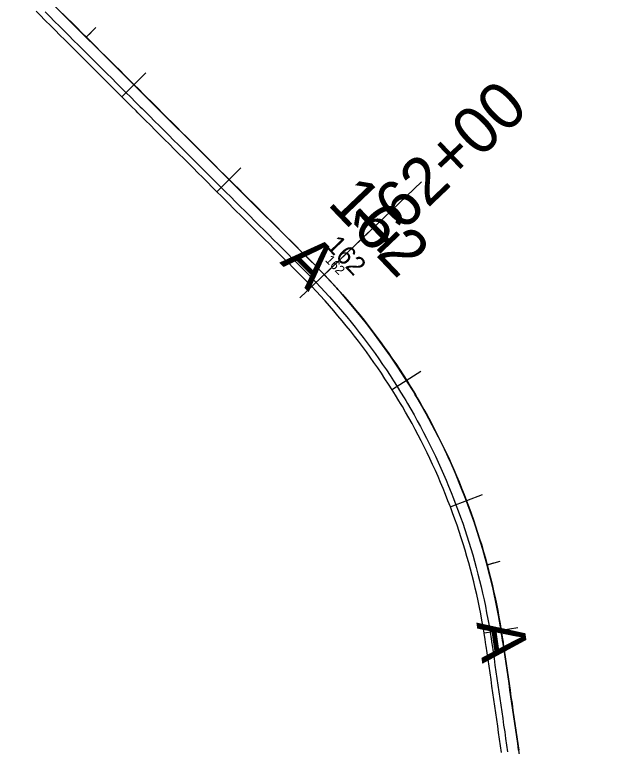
# Model space of a CAD drawing. Extents: x 1823824 to 1861612, y 706975 to 726130.
# Drawn here: x 1826051.2 to 1826141.7, y 715288.9 to 715397.8 of the extents above; entities that cross this region are included whole.
import ezdxf

# ---------------------------------------------------------------- set-up
doc = ezdxf.new("R2010")
doc.units = 0
for name, color, linetype in [('DR_X_Flood_Boundary', 7, 'Continuous'), ('GE_X_CL_10', 7, 'Continuous'), ('GE_X_CL_100', 7, 'Continuous'), ('GE_X_CL_20', 7, 'Continuous'), ('GE_X_CL_200', 7, 'Continuous'), ('GE_X_CL_50', 7, 'Continuous'), ('SC_Scratch3', 7, 'Continuous'), ('SC_Scratch5', 7, 'Continuous'), ('SC_Scratch6', 7, 'Continuous')]:
    doc.layers.add(name, color=color, linetype=linetype)

msp = doc.modelspace()

# ---------------------------------------------------------------- linework, layer by layer
at = {"layer": 'DR_X_Flood_Boundary'}
for p, q in [((1826051.17, 715405.06), (1826095.44, 715360.91)), ((1826123.8, 715304.42), (1826141.7, 715180.65))]:
    msp.add_line(p, q, dxfattribs=at)
msp.add_arc((1826024.83, 715290.1), 100, 8.2313, 45.0774, dxfattribs=at)
at = {"layer": 'GE_X_CL_10'}
for p, q in [((1826061.82, 715394.44), (1826062.53, 715395.15)), ((1826097.2, 715359.11), (1826097.93, 715359.8)), ((1826121.43, 715315.96), (1826122.39, 715316.22))]:
    msp.add_line(p, q, dxfattribs=at)
at = {"layer": 'GE_X_CL_100'}
msp.add_line((1826097.2, 715359.11), (1826104.44, 715366.01), dxfattribs=at)
at = {"layer": 'GE_X_CL_20'}
for p, q in [((1826061.82, 715394.44), (1826063.23, 715395.86)), ((1826097.2, 715359.11), (1826098.65, 715360.49)), ((1826121.43, 715315.96), (1826123.36, 715316.48))]:
    msp.add_line(p, q, dxfattribs=at)
at = {"layer": 'GE_X_CL_200'}
msp.add_line((1826097.2, 715359.11), (1826111.68, 715372.91), dxfattribs=at)
at = {"layer": 'GE_X_CL_50'}
msp.add_line((1826097.2, 715359.11), (1826100.82, 715362.56), dxfattribs=at)
at = {"layer": 'SC_Scratch3'}
for points in [[(1826110.74, 715336.1), (1826110.27, 715336.96), (1826109.8, 715337.81), (1826109.32, 715338.66), (1826108.83, 715339.5), (1826108.56, 715339.95), (1826108.33, 715340.34), (1826107.82, 715341.17), (1826107.31, 715342), (1826106.79, 715342.82), (1826106.25, 715343.63), (1826105.71, 715344.45), (1826105.17, 715345.25), (1826104.61, 715346.05), (1826104.05, 715346.85), (1826103.48, 715347.64), (1826102.9, 715348.42), (1826102.31, 715349.2), (1826101.72, 715349.97), (1826101.11, 715350.74), (1826100.5, 715351.5), (1826099.89, 715352.25), (1826099.26, 715353), (1826098.63, 715353.74), (1826097.99, 715354.47), (1826097.34, 715355.2), (1826097.19, 715355.37), (1826096.69, 715355.92), (1826096.02, 715356.64), (1826095.35, 715357.35), (1826094.68, 715358.05), (1826094, 715358.74), (1826093.64, 715359.1), (1826093.3, 715359.44), (1826092.59, 715360.15), (1826091.88, 715360.85), (1826091.17, 715361.56), (1826090.47, 715362.27), (1826089.76, 715362.97), (1826089.05, 715363.68), (1826088.34, 715364.39), (1826087.63, 715365.09), (1826086.93, 715365.8), (1826086.22, 715366.5), (1826085.51, 715367.21), (1826084.8, 715367.92), (1826084.09, 715368.62), (1826083.44, 715369.27), (1826083.39, 715369.33), (1826082.68, 715370.03), (1826081.97, 715370.74), (1826081.26, 715371.45), (1826080.55, 715372.15), (1826079.84, 715372.86), (1826079.14, 715373.57), (1826078.43, 715374.27), (1826077.72, 715374.98), (1826077.01, 715375.68), (1826076.31, 715376.39), (1826075.6, 715377.1), (1826074.89, 715377.8), (1826074.18, 715378.51), (1826073.47, 715379.22), (1826072.77, 715379.92), (1826072.06, 715380.63), (1826071.35, 715381.34), (1826070.64, 715382.04), (1826069.94, 715382.75), (1826069.51, 715383.18), (1826069.23, 715383.46), (1826068.52, 715384.16), (1826067.81, 715384.87), (1826067.11, 715385.58), (1826066.4, 715386.28), (1826065.69, 715386.99), (1826064.98, 715387.7), (1826064.28, 715388.4), (1826063.57, 715389.11), (1826062.86, 715389.82), (1826062.15, 715390.52), (1826061.45, 715391.23), (1826060.74, 715391.94), (1826060.03, 715392.64), (1826059.32, 715393.35), (1826058.62, 715394.06), (1826057.91, 715394.76), (1826057.2, 715395.47), (1826056.49, 715396.17), (1826055.78, 715396.88), (1826055.57, 715397.09), (1826055.08, 715397.59), (1826054.37, 715398.29)], [(1826055.69, 715398.21), (1826056.19, 715397.71), (1826056.4, 715397.5), (1826057.11, 715396.79), (1826057.82, 715396.09), (1826058.53, 715395.38), (1826059.23, 715394.68), (1826059.94, 715393.97), (1826060.65, 715393.26), (1826061.36, 715392.56), (1826062.07, 715391.85), (1826062.77, 715391.15), (1826063.48, 715390.44), (1826064.19, 715389.73), (1826064.9, 715389.03)], [(1826113, 715337.31), (1826112.52, 715338.19), (1826112.03, 715339.06), (1826111.54, 715339.93), (1826111.04, 715340.8), (1826110.76, 715341.26), (1826110.53, 715341.66), (1826110.01, 715342.51), (1826109.48, 715343.36), (1826108.94, 715344.2), (1826108.4, 715345.04), (1826107.84, 715345.88), (1826107.28, 715346.7), (1826106.71, 715347.52), (1826106.13, 715348.34), (1826105.55, 715349.15), (1826104.95, 715349.96), (1826104.35, 715350.75), (1826103.74, 715351.55), (1826103.12, 715352.33), (1826102.49, 715353.11), (1826101.86, 715353.88), (1826101.22, 715354.65), (1826100.57, 715355.41), (1826099.91, 715356.17), (1826099.25, 715356.91), (1826099.09, 715357.09), (1826098.58, 715357.66), (1826097.9, 715358.39), (1826097.21, 715359.12), (1826096.52, 715359.84), (1826095.82, 715360.55), (1826095.45, 715360.92), (1826095.11, 715361.26), (1826094.4, 715361.96), (1826093.69, 715362.67), (1826092.98, 715363.38), (1826092.28, 715364.08), (1826091.57, 715364.79), (1826090.86, 715365.49), (1826090.15, 715366.2), (1826089.44, 715366.91), (1826088.74, 715367.61), (1826088.03, 715368.32), (1826087.32, 715369.02), (1826086.61, 715369.73), (1826085.9, 715370.44), (1826085.25, 715371.09), (1826085.2, 715371.14), (1826084.49, 715371.85), (1826083.78, 715372.56), (1826083.07, 715373.26), (1826082.36, 715373.97), (1826081.66, 715374.67), (1826080.95, 715375.38), (1826080.24, 715376.09), (1826079.53, 715376.79), (1826078.82, 715377.5), (1826078.11, 715378.2), (1826077.41, 715378.91), (1826076.7, 715379.62), (1826075.99, 715380.32), (1826075.28, 715381.03), (1826074.57, 715381.74), (1826073.87, 715382.44), (1826073.16, 715383.15), (1826072.45, 715383.85), (1826071.74, 715384.56), (1826071.31, 715384.99), (1826071.03, 715385.27), (1826070.33, 715385.97), (1826069.62, 715386.68), (1826068.91, 715387.38), (1826068.2, 715388.09), (1826067.49, 715388.8), (1826066.79, 715389.5), (1826066.08, 715390.21), (1826065.37, 715390.92), (1826064.66, 715391.62), (1826063.95, 715392.33), (1826063.25, 715393.03), (1826062.54, 715393.74), (1826061.83, 715394.45), (1826061.12, 715395.15), (1826060.41, 715395.86), (1826059.71, 715396.56), (1826059, 715397.27), (1826058.29, 715397.98)], [(1826058.3, 715397.98), (1826059, 715397.28), (1826059.71, 715396.57), (1826060.42, 715395.86), (1826061.13, 715395.16), (1826061.84, 715394.45), (1826062.54, 715393.75), (1826063.25, 715393.04), (1826063.96, 715392.33), (1826064.67, 715391.63), (1826065.38, 715390.92), (1826066.08, 715390.22)], [(1826066.08, 715390.22), (1826066.79, 715389.51), (1826067.5, 715388.8), (1826068.21, 715388.1), (1826068.92, 715387.39), (1826069.62, 715386.69), (1826070.33, 715385.98), (1826071.04, 715385.27), (1826071.32, 715385), (1826071.75, 715384.57), (1826072.46, 715383.86), (1826073.16, 715383.15), (1826073.87, 715382.45), (1826074.58, 715381.74), (1826075.29, 715381.04), (1826076, 715380.33), (1826076.71, 715379.62), (1826077.41, 715378.92), (1826078.12, 715378.21), (1826078.83, 715377.51), (1826079.54, 715376.8), (1826080.25, 715376.09), (1826080.95, 715375.39), (1826081.66, 715374.68), (1826082.37, 715373.97), (1826083.08, 715373.27), (1826083.79, 715372.56), (1826084.49, 715371.86), (1826085.2, 715371.15), (1826085.26, 715371.09), (1826085.91, 715370.44), (1826086.62, 715369.74), (1826087.33, 715369.03), (1826088.03, 715368.33), (1826088.74, 715367.62), (1826089.45, 715366.91), (1826090.16, 715366.21), (1826090.87, 715365.5), (1826091.57, 715364.79), (1826092.28, 715364.09), (1826092.99, 715363.38), (1826093.7, 715362.68), (1826094.41, 715361.97), (1826095.11, 715361.26), (1826095.46, 715360.92), (1826095.82, 715360.56), (1826096.52, 715359.84), (1826097.22, 715359.12), (1826097.9, 715358.4), (1826098.58, 715357.66), (1826099.1, 715357.09), (1826099.25, 715356.92), (1826099.92, 715356.17), (1826100.58, 715355.42), (1826101.23, 715354.66), (1826101.87, 715353.89), (1826102.5, 715353.12), (1826103.13, 715352.34), (1826103.75, 715351.55), (1826104.36, 715350.76), (1826104.96, 715349.96), (1826105.55, 715349.16), (1826106.14, 715348.35), (1826106.72, 715347.53), (1826107.29, 715346.71), (1826107.85, 715345.88), (1826108.4, 715345.05), (1826108.95, 715344.21), (1826109.49, 715343.37), (1826110.01, 715342.52), (1826110.53, 715341.66), (1826110.77, 715341.27), (1826111.05, 715340.8), (1826111.55, 715339.94), (1826112.04, 715339.07), (1826112.53, 715338.19), (1826113, 715337.31), (1826113.47, 715336.43), (1826113.93, 715335.54), (1826114.38, 715334.65), (1826114.82, 715333.75), (1826115.25, 715332.85), (1826115.68, 715331.94), (1826116.09, 715331.03), (1826116.49, 715330.12), (1826116.89, 715329.2), (1826117.28, 715328.28), (1826117.65, 715327.35), (1826118.02, 715326.42), (1826118.38, 715325.49), (1826118.73, 715324.55), (1826119.07, 715323.61), (1826119.4, 715322.66), (1826119.72, 715321.72), (1826120.03, 715320.77), (1826120.33, 715319.81), (1826120.63, 715318.86), (1826120.91, 715317.9), (1826121.18, 715316.93), (1826121.45, 715315.97), (1826121.7, 715315)], [(1826064.9, 715389.03), (1826065.61, 715388.32), (1826066.31, 715387.61), (1826067.02, 715386.91), (1826067.73, 715386.2), (1826068.44, 715385.5), (1826069.15, 715384.79), (1826069.85, 715384.08), (1826070.13, 715383.81), (1826070.56, 715383.38), (1826071.27, 715382.67), (1826071.98, 715381.97), (1826072.69, 715381.26), (1826073.4, 715380.55), (1826074.1, 715379.85), (1826074.81, 715379.14), (1826075.52, 715378.43), (1826076.23, 715377.73), (1826076.94, 715377.02), (1826077.64, 715376.32), (1826078.35, 715375.61), (1826079.06, 715374.9), (1826079.77, 715374.2), (1826080.48, 715373.49), (1826081.18, 715372.79), (1826081.89, 715372.08), (1826082.6, 715371.37), (1826083.31, 715370.67), (1826084.02, 715369.96), (1826084.07, 715369.9), (1826084.72, 715369.25), (1826085.43, 715368.55), (1826086.14, 715367.84), (1826086.85, 715367.14), (1826087.56, 715366.43), (1826088.26, 715365.72), (1826088.97, 715365.02), (1826089.68, 715364.31), (1826090.39, 715363.61), (1826091.1, 715362.9), (1826091.8, 715362.19), (1826092.51, 715361.49), (1826093.22, 715360.78), (1826093.93, 715360.07), (1826094.27, 715359.73), (1826094.63, 715359.37), (1826095.32, 715358.67), (1826096, 715357.96), (1826096.68, 715357.25), (1826097.34, 715356.53), (1826097.85, 715355.97), (1826098, 715355.8), (1826098.66, 715355.06), (1826099.3, 715354.32), (1826099.94, 715353.57), (1826100.57, 715352.82), (1826101.2, 715352.06), (1826101.81, 715351.29), (1826102.42, 715350.52), (1826103.02, 715349.74), (1826103.61, 715348.96), (1826104.2, 715348.16), (1826104.77, 715347.37), (1826105.34, 715346.57), (1826105.9, 715345.76), (1826106.46, 715344.94), (1826107, 715344.13), (1826107.54, 715343.3), (1826108.06, 715342.47), (1826108.58, 715341.64), (1826109.1, 715340.8), (1826109.33, 715340.41), (1826109.6, 715339.95), (1826110.09, 715339.1), (1826110.58, 715338.25), (1826111.06, 715337.39), (1826111.52, 715336.52), (1826111.98, 715335.65), (1826112.43, 715334.78), (1826112.88, 715333.9), (1826113.31, 715333.02), (1826113.74, 715332.13), (1826114.15, 715331.24), (1826114.56, 715330.34), (1826114.96, 715329.44), (1826115.34, 715328.54), (1826115.72, 715327.63), (1826116.1, 715326.72), (1826116.46, 715325.81), (1826116.81, 715324.89), (1826117.15, 715323.97), (1826117.49, 715323.04), (1826117.81, 715322.12), (1826118.13, 715321.19), (1826118.43, 715320.25), (1826118.73, 715319.31), (1826119.02, 715318.37), (1826119.3, 715317.43), (1826119.56, 715316.48), (1826119.82, 715315.53), (1826120.07, 715314.58)], [(1826126.13, 715288.38), (1826125.99, 715289.37), (1826125.84, 715290.36), (1826125.7, 715291.35), (1826125.56, 715292.34), (1826125.41, 715293.33), (1826125.27, 715294.32), (1826125.13, 715295.31), (1826124.98, 715296.3), (1826124.84, 715297.29), (1826124.7, 715298.28), (1826124.55, 715299.27), (1826124.41, 715300.26), (1826124.27, 715301.25), (1826124.12, 715302.24), (1826123.98, 715303.23), (1826123.84, 715304.22), (1826123.81, 715304.42), (1826123.69, 715305.2), (1826123.54, 715306.19), (1826123.37, 715307.18), (1826123.19, 715308.16), (1826123.01, 715309.15), (1826122.81, 715310.13), (1826122.61, 715311.11), (1826122.39, 715312.08), (1826122.17, 715313.06), (1826121.93, 715314.03), (1826121.69, 715315), (1826121.44, 715315.97), (1826121.17, 715316.93), (1826120.9, 715317.89), (1826120.62, 715318.85), (1826120.32, 715319.81), (1826120.02, 715320.76), (1826119.71, 715321.71), (1826119.39, 715322.66), (1826119.06, 715323.6), (1826118.72, 715324.54), (1826118.37, 715325.48), (1826118.01, 715326.42), (1826117.65, 715327.35), (1826117.27, 715328.27), (1826116.88, 715329.19), (1826116.49, 715330.11), (1826116.08, 715331.03), (1826115.67, 715331.94), (1826115.25, 715332.84), (1826114.81, 715333.75), (1826114.37, 715334.64), (1826113.92, 715335.54), (1826113.46, 715336.43), (1826113, 715337.31)], [(1826123.57, 715288.01), (1826123.43, 715289), (1826123.29, 715289.99), (1826123.15, 715290.98), (1826123.01, 715291.97), (1826122.87, 715292.96), (1826122.73, 715293.95), (1826122.59, 715294.94), (1826122.44, 715295.93), (1826122.3, 715296.92), (1826122.16, 715297.91), (1826122.02, 715298.9), (1826121.87, 715299.89), (1826121.73, 715300.88), (1826121.59, 715301.87), (1826121.44, 715302.86), (1826121.3, 715303.85), (1826121.27, 715304.05), (1826121.16, 715304.82), (1826121.01, 715305.78), (1826120.85, 715306.74), (1826120.67, 715307.7), (1826120.49, 715308.66), (1826120.3, 715309.61), (1826120.1, 715310.57), (1826119.89, 715311.52), (1826119.67, 715312.47), (1826119.45, 715313.42), (1826119.21, 715314.36), (1826118.96, 715315.3), (1826118.7, 715316.24), (1826118.44, 715317.18), (1826118.16, 715318.12), (1826117.88, 715319.05), (1826117.58, 715319.98), (1826117.28, 715320.9), (1826116.97, 715321.83), (1826116.64, 715322.74), (1826116.31, 715323.66), (1826115.97, 715324.57), (1826115.62, 715325.48), (1826115.26, 715326.39), (1826114.9, 715327.29), (1826114.52, 715328.19), (1826114.14, 715329.09), (1826113.74, 715329.98), (1826113.34, 715330.87), (1826112.93, 715331.75), (1826112.51, 715332.63), (1826112.08, 715333.5), (1826111.64, 715334.37), (1826111.19, 715335.24), (1826110.74, 715336.1)], [(1826120.07, 715314.58), (1826120.31, 715313.63), (1826120.54, 715312.67), (1826120.76, 715311.72), (1826120.98, 715310.76), (1826121.18, 715309.79), (1826121.37, 715308.83), (1826121.55, 715307.86), (1826121.72, 715306.89), (1826121.89, 715305.92), (1826122.04, 715304.95), (1826122.16, 715304.18), (1826122.19, 715303.98), (1826122.33, 715302.99), (1826122.47, 715302), (1826122.61, 715301.01), (1826122.76, 715300.02), (1826122.9, 715299.03), (1826123.04, 715298.04), (1826123.19, 715297.05), (1826123.33, 715296.06), (1826123.47, 715295.07), (1826123.62, 715294.08), (1826123.76, 715293.09), (1826123.9, 715292.1), (1826124.05, 715291.11), (1826124.19, 715290.12), (1826124.33, 715289.13), (1826124.48, 715288.14)], [(1826121.7, 715315), (1826121.94, 715314.03), (1826122.18, 715313.06), (1826122.4, 715312.08), (1826122.62, 715311.11), (1826122.82, 715310.13), (1826123.02, 715309.15), (1826123.2, 715308.16), (1826123.38, 715307.18), (1826123.54, 715306.19), (1826123.7, 715305.21), (1826123.82, 715304.42), (1826123.85, 715304.22), (1826123.99, 715303.23), (1826124.13, 715302.24), (1826124.28, 715301.25), (1826124.42, 715300.26), (1826124.56, 715299.27), (1826124.71, 715298.28), (1826124.85, 715297.29), (1826124.99, 715296.3), (1826125.14, 715295.31), (1826125.28, 715294.32), (1826125.42, 715293.33), (1826125.57, 715292.34), (1826125.71, 715291.35), (1826125.85, 715290.36), (1826125.99, 715289.37), (1826126.14, 715288.38)]]:
    msp.add_lwpolyline(points, dxfattribs=at)
at = {"layer": 'SC_Scratch5'}
for points in [[(1826070.67, 715389.15), (1826067.14, 715385.61)], [(1826084.83, 715375.02), (1826081.3, 715371.48)], [(1826100.82, 715362.56), (1826093.58, 715355.66)], [(1826111.59, 715344.69), (1826107.35, 715342.02)], [(1826120.7, 715326.36), (1826116.02, 715324.59)], [(1826125.99, 715306.59), (1826121.06, 715305.79)]]:
    msp.add_lwpolyline(points, dxfattribs=at)

# ---------------------------------------------------------------- texts
at = {"layer": 'GE_X_CL_10'}
msp.add_text('162', height=1.4, rotation=313.6357, dxfattribs=at).set_placement((1826097.27, 715361.21))
at = {"layer": 'GE_X_CL_20'}
msp.add_text('162', height=2.8, rotation=313.6357, dxfattribs=at).set_placement((1826097.34, 715363.31))
at = {"layer": 'GE_X_CL_50'}
msp.add_text('162', height=7, rotation=313.6357, dxfattribs=at).set_placement((1826097.55, 715369.61))
at = {"layer": 'SC_Scratch5'}
msp.add_text('162+00', height=7, rotation=43.6357, dxfattribs=at).set_placement((1826105.05, 715361.75))
at = {"layer": 'SC_Scratch6'}
for rotation, p in [(315.0774, (1826090.49, 715360.9)), (278.2313, (1826119.83, 715307.38))]:
    msp.add_text('A', height=7, rotation=rotation, dxfattribs=at).set_placement(p)

doc.saveas('drawing.dxf')
